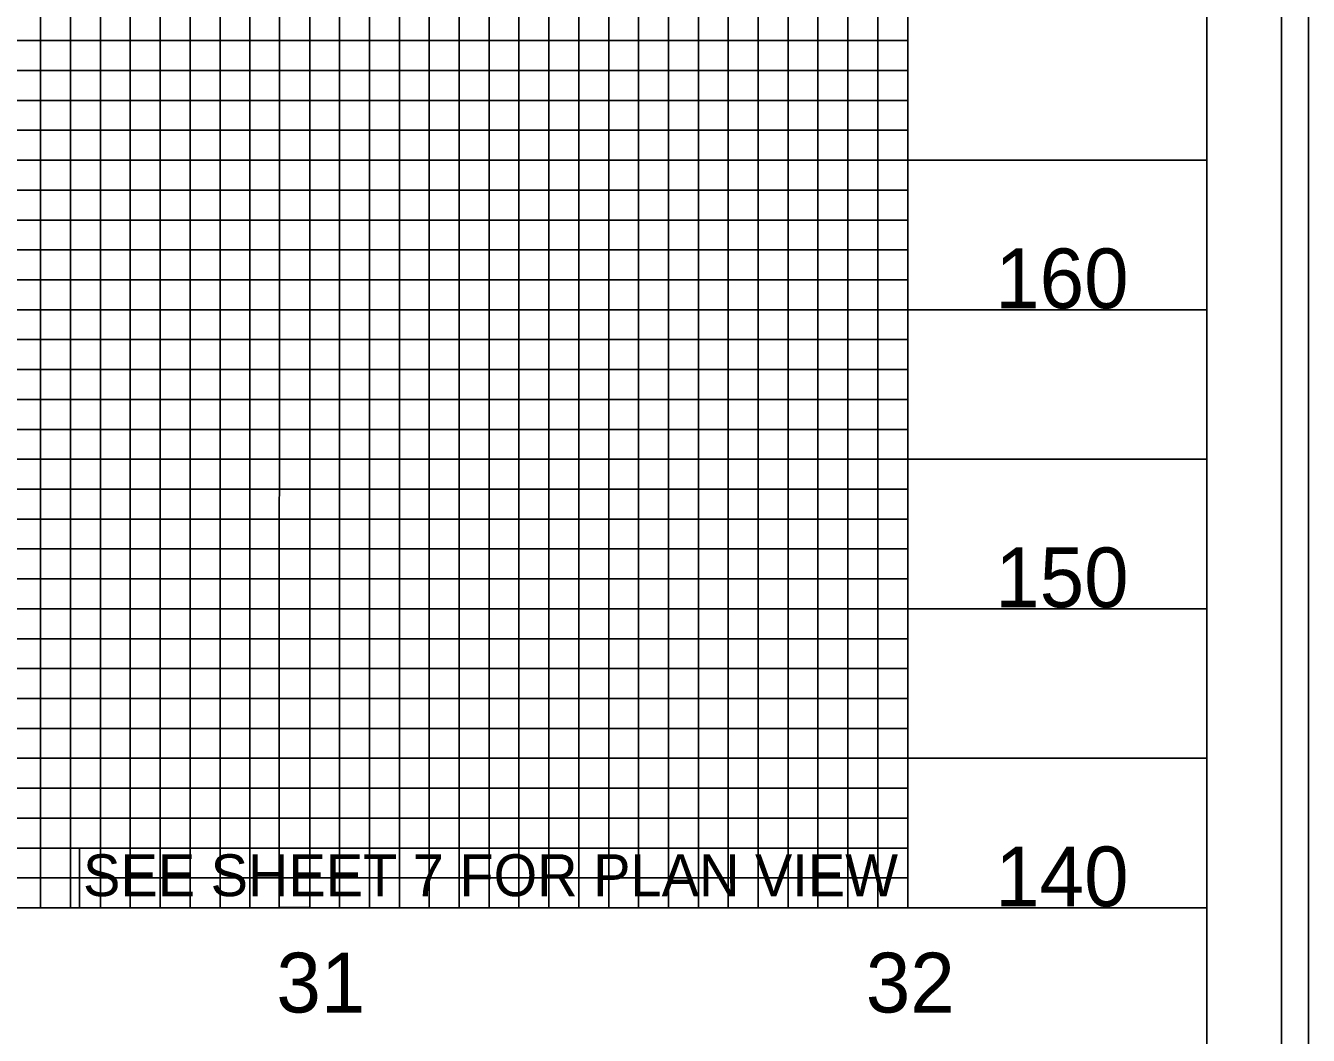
# Model space of a CAD drawing. Extents: x 1779926 to 1781610, y 620464 to 621564.
# Drawn here: x 1781395.5 to 1781610, y 621017.9 to 621186.7 of the extents above; entities that cross this region are included whole.
import ezdxf

# ---------------------------------------------------------------- set-up
doc = ezdxf.new("R2010")
doc.units = 0
for name, color, linetype in [('Exist Vertical Profile Horizontal Axis Label Major', 7, 'Continuous'), ('Exist Vertical Profile Vertical Axis Label', 7, 'Continuous'), ('Prop DSN Text', 7, 'Continuous'), ('Prop Grid Mask', 7, 'Continuous'), ('Scratch_Level_0', 7, 'Continuous'), ('Sheet DOT Grid CELL', 7, 'Continuous'), ('Sheet Layout Profile Border Port 1', 7, 'Continuous'), ('Sheet Plot Border Inside CELL', 7, 'Continuous'), ('Sheet Plot Border Outside CELL', 7, 'Continuous'), ('Sheet Profile CELL', 7, 'Continuous'), ('Sheet Profile Grid Major CELL', 7, 'Continuous'), ('Sheet Profile Grid Middle CELL', 7, 'Continuous'), ('Sheet Profile Grid Minor CELL', 7, 'Continuous')]:
    doc.layers.add(name, color=color, linetype=linetype)

msp = doc.modelspace()

# ---------------------------------------------------------------- linework, layer by layer
at = {"layer": 'Prop Grid Mask'}
msp.add_lwpolyline([(1781542.96, 621049.19), (1781404.46, 621049.19), (1781404.46, 621039.19), (1781542.96, 621039.19)], close=True, dxfattribs=at)
at = {"layer": 'Scratch_Level_0'}
msp.add_lwpolyline([(1780192.96, 621039.19), (1780192.96, 621539.19), (1781392.96, 621539.19), (1781392.96, 621314.19), (1781542.96, 621314.19), (1781542.96, 621039.19)], close=True, dxfattribs=at)
at = {"layer": 'Sheet DOT Grid CELL'}
for p, q in [((1781442.96, 621039.19), (1781442.96, 621314.19)), ((1781492.96, 621039.19), (1781492.96, 621314.19)), ((1781542.96, 621039.19), (1781542.96, 621314.19)), ((1781592.96, 621139.19), (1780092.96, 621139.19)), ((1781592.96, 621089.19), (1780092.96, 621089.19))]:
    msp.add_line(p, q, dxfattribs=at)
at = {"layer": 'Sheet Layout Profile Border Port 1'}
msp.add_lwpolyline([(1781392.96, 621539.19), (1781392.9, 621314.19), (1781532.96, 621314.19), (1781532.96, 621039.19), (1780182.96, 621039.19), (1780182.96, 621539.19)], close=True, dxfattribs=at)
msp.add_lwpolyline([(1780142.96, 621378.14), (1780142.96, 621039.19), (1781542.96, 621039.19), (1781542.96, 621314.19)], dxfattribs=at)
at = {"layer": 'Sheet Plot Border Inside CELL'}
msp.add_lwpolyline([(1779938.96, 620486.64), (1781605.46, 620486.64), (1781605.46, 621541.74), (1779938.96, 621541.74)], close=True, dxfattribs=at)
at = {"layer": 'Sheet Plot Border Outside CELL'}
msp.add_lwpolyline([(1779925.96, 620464.19), (1781609.96, 620464.19), (1781609.96, 621564.19), (1779925.96, 621564.19)], close=True, dxfattribs=at)
at = {"layer": 'Sheet Profile CELL'}
msp.add_line((1780092.96, 621039.19), (1781592.96, 621039.19), dxfattribs=at)
msp.add_lwpolyline([(1781592.96, 621539.19), (1780092.96, 621539.19), (1780092.96, 620489.19), (1781592.96, 620489.19)], close=True, dxfattribs=at)
at = {"layer": 'Sheet Profile Grid Major CELL'}
for points in [[(1781542.96, 621314.19), (1781542.96, 621039.19), (1781592.96, 621039.19), (1781592.96, 621389.19)], [(1781442.96, 621314.19), (1781442.96, 621039.19), (1781492.96, 621039.19), (1781492.96, 621039.19), (1781492.96, 621314.19)], [(1781592.96, 621139.19), (1780092.96, 621139.19), (1780092.96, 621139.19), (1780092.96, 621089.19), (1781592.96, 621089.19)]]:
    msp.add_lwpolyline(points, dxfattribs=at)
at = {"layer": 'Sheet Profile Grid Middle CELL'}
for points in [[(1781117.96, 621539.19), (1781167.96, 621539.19), (1781167.96, 621039.19), (1781217.96, 621039.19), (1781217.96, 621539.19), (1781267.96, 621539.19), (1781267.96, 621039.19), (1781317.96, 621039.19), (1781317.96, 621539.19), (1781367.96, 621539.19), (1781367.96, 621039.19), (1781417.96, 621039.19), (1781417.96, 621314.19)], [(1781417.96, 621301.99), (1781417.96, 621039.19), (1781467.96, 621039.19), (1781467.96, 621314.19)], [(1781467.96, 621301.99), (1781467.96, 621039.19), (1781517.96, 621039.19), (1781517.96, 621314.19)], [(1781592.96, 621164.19), (1780092.96, 621164.19), (1780092.96, 621114.19), (1781592.96, 621114.19)], [(1781592.96, 621064.19), (1780092.96, 621064.19)]]:
    msp.add_lwpolyline(points, dxfattribs=at)
at = {"layer": 'Sheet Profile Grid Minor CELL'}
for p, q in [((1780142.96, 621184.19), (1781542.96, 621184.19)), ((1781542.96, 621179.19), (1780142.96, 621179.19)), ((1780142.96, 621174.19), (1781542.96, 621174.19)), ((1781542.96, 621169.19), (1780142.96, 621169.19)), ((1780142.96, 621159.19), (1781542.96, 621159.19)), ((1781542.96, 621154.19), (1780142.96, 621154.19)), ((1781542.96, 621149.19), (1780142.96, 621149.19)), ((1781542.96, 621144.19), (1780142.96, 621144.19)), ((1780142.96, 621134.19), (1781542.96, 621134.19)), ((1781542.96, 621129.19), (1780142.96, 621129.19)), ((1780142.96, 621124.19), (1781542.96, 621124.19)), ((1781542.96, 621119.19), (1780142.96, 621119.19)), ((1780142.96, 621109.19), (1781542.96, 621109.19)), ((1781542.96, 621104.19), (1780142.96, 621104.19)), ((1780142.96, 621099.19), (1781542.96, 621099.19)), ((1781542.96, 621094.19), (1780142.96, 621094.19)), ((1780142.96, 621084.19), (1781542.96, 621084.19)), ((1781542.96, 621079.19), (1780142.96, 621079.19)), ((1780142.96, 621074.19), (1781542.96, 621074.19)), ((1781542.96, 621069.19), (1780142.96, 621069.19)), ((1780142.96, 621059.19), (1781542.96, 621059.19)), ((1781542.96, 621054.19), (1780142.96, 621054.19)), ((1780142.96, 621049.19), (1781542.96, 621049.19))]:
    msp.add_line(p, q, dxfattribs=at)
for points in [[(1781397.96, 621314.19), (1781397.96, 621039.19), (1781402.96, 621039.19), (1781402.96, 621314.19)], [(1781407.96, 621314.19), (1781407.96, 621039.19), (1781412.96, 621039.19), (1781412.96, 621314.19)], [(1781422.96, 621314.19), (1781422.96, 621039.19), (1781422.96, 621039.19), (1781427.96, 621039.19), (1781432.96, 621039.19), (1781432.96, 621314.19)], [(1781427.96, 621314.19), (1781427.96, 621039.19)], [(1781437.94, 621314.19), (1781437.86, 621039.24), (1781442.86, 621039.24), (1781447.96, 621039.19), (1781447.96, 621314.19)], [(1781447.96, 621301.99), (1781447.96, 621039.19), (1781452.96, 621039.19), (1781452.96, 621314.19)], [(1781457.96, 621314.19), (1781457.96, 621039.19), (1781462.96, 621039.19), (1781462.96, 621314.19)], [(1781472.96, 621314.19), (1781472.96, 621039.19), (1781477.96, 621039.19), (1781477.96, 621314.19)], [(1781482.96, 621314.19), (1781482.96, 621039.19), (1781487.96, 621039.19), (1781487.96, 621314.19)], [(1781497.96, 621314.19), (1781497.96, 621039.19), (1781502.96, 621039.19), (1781502.96, 621314.19)], [(1781507.96, 621314.19), (1781507.96, 621039.19), (1781512.96, 621039.19), (1781512.96, 621314.19)], [(1781522.96, 621314.19), (1781522.96, 621039.19), (1781527.96, 621039.19), (1781527.96, 621314.19)], [(1781532.96, 621314.19), (1781532.96, 621039.19), (1781537.96, 621039.19), (1781537.96, 621314.19)], [(1781542.96, 621044.19), (1780142.96, 621044.19)]]:
    msp.add_lwpolyline(points, dxfattribs=at)

# ---------------------------------------------------------------- texts
at = {"layer": 'Exist Vertical Profile Horizontal Axis Label Major'}
for s, p in [('31', (1781437.39, 621021.69)), ('32', (1781535.96, 621021.69))]:
    msp.add_text(s, height=10, dxfattribs=at).set_placement(p)
at = {"layer": 'Exist Vertical Profile Vertical Axis Label'}
for s, p in [('160', (1781557.59, 621139.44)), ('150', (1781557.59, 621089.44)), ('140', (1781557.59, 621039.44))]:
    msp.add_text(s, height=10, dxfattribs=at).set_placement(p)
at = {"layer": 'Prop DSN Text'}
msp.add_text('SEE SHEET 7 FOR PLAN VIEW', height=7, dxfattribs=at).set_placement((1781405.06, 621041.14))

doc.saveas('drawing.dxf')
